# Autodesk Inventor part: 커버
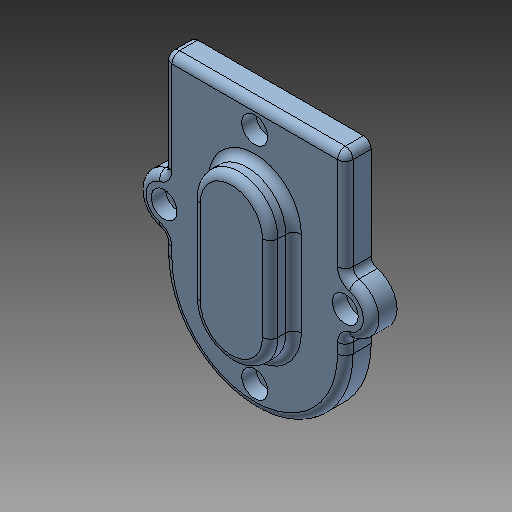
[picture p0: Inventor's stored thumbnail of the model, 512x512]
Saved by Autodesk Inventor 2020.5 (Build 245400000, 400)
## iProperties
Created: 2024-02
Part Number: 커버
Material: 알루미늄 6061
Document SubType Name: Modeling
Designer: mdu-01
Density: 1 g/cm^3
Appearance: 기본값(1)
Author: mdu-01
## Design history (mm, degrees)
sketch "스케치1"
  geometry: L1 (14, -3.702)-(14, -14.074) reference; L2 (-14, -14.074)-(-14, -3.702) reference; L3 (35, 3.761)-(35, 39.612) reference; L4 (32, 42.612)-(-32, 42.612) reference; L5 (-35, 39.612)-(-35, 3.761) reference; L6 (-35, -21.537)-(-35, -25.388) reference; L7 (35, -25.388)-(35, -21.537) reference; C1 r 2.75 at (0, -51.388) reference; C2 r 2.75 at (-35, -8.888) reference; C3 r 2.75 at (35, -8.888) reference; C4 r 2.75 at (0, 33.612) reference; A1 r 18 centre (0, 7.612) between (14, -3.702) and (-14, -3.702) reference; A2 r 18 centre (0, -25.388) between (-14, -14.074) and (14, -14.074) reference; A3 r 3 centre (38, 3.761) between (35, 3.761) and (37.308, 0.842) reference; A4 r 3 centre (32, 39.612) between (35, 39.612) and (32, 42.612) reference; A5 r 3 centre (-32, 39.612) between (-32, 42.612) and (-35, 39.612) reference; A6 r 3 centre (-38, 3.761) between (-37.308, 0.842) and (-35, 3.761) reference; A7 r 10 centre (-35, -8.888) between (-37.308, 0.842) and (-37.308, -18.618) reference; A8 r 3 centre (-38, -21.537) between (-35, -21.537) and (-37.308, -18.618) reference; A9 r 35 centre (0, -25.388) between (-35, -25.388) and (35, -25.388) reference; A10 r 3 centre (38, -21.537) between (37.308, -18.618) and (35, -21.537) reference; A11 r 10 centre (35, -8.888) between (37.308, -18.618) and (37.308, 0.842) reference; 1 further point
extrude "돌출1" new body sketch "스케치1" distance "d0" = 10; taper "d1" = 0 deg
sketch "스케치2"
  geometry: L1 (-15, 7.612)-(-15, -25.388); L2 (15, 7.612)-(15, -25.388); A1 r 15 centre (0, -25.388) between (-15, -25.388) and (15, -25.388); A2 r 15 centre (0, 7.612) between (15, 7.612) and (-15, 7.612); 3 further points
  constraints: 4 end point, 4 point on circle, 4 tangent, 2 centre point, 2 coincident
  dimensions: "d2" = 30 diameter of A1; "d3" = 30 diameter of A2
extrude "돌출2" join sketch "스케치2" distance "d4" = 9; taper "d5" = 0 deg
fillet "모깎기1" dims "d6" = 3
sketch "스케치3"
  geometry: L1 (-25.388, 0)-(-25.388, 14.041); L2 (-25.388, 16)-(-25.388, 19) reference; L3 (-25.388, 14.041)-(-18.388, 10); L4 (-18.388, 10)-(-15.388, 10); L5 (-15.388, 10)-(-15.388, 0); L6 (0.842, 0)-(-18.618, 0) reference; L7 (-15.388, 0)-(-25.388, 0); 2 further points
  constraints: 10 end point, 2 collinear, 1 parallel, 1 point on line
  dimensions: "d7" = 10 distance between parallel lines of L4 L7; "d9" = 14 diameter of L3.end L1; "d10" = 60 deg angle of L1 L3; "d11" = 20 diameter of L5 L1
revolve "회전1" sketch "스케치3" stored, may be unused: angle "d12" = 90 deg
chamfer "모따기1" distance "d13" = 1; stored, may be unused: second distance "d14" = 2, angle "d15" = 45 deg
sketch "스케치4"
  geometry: 5 further points
hole "구멍1" sketch "스케치4" at (35, -8.888), (-35, -8.888), (0, 33.612), (0, -51.388) diameter "d19" = 5.5; stored, may be unused: countersink angle "d23" = 90 deg, drill point angle "d25" = 118 deg; dims "d20" = 6, "d21" = 10, "d22" = 5.5, "d24" = 8
node "솔리드1"
pattern_linear "직사각형 패턴1" dims "d18" = 33
node "참조1"
